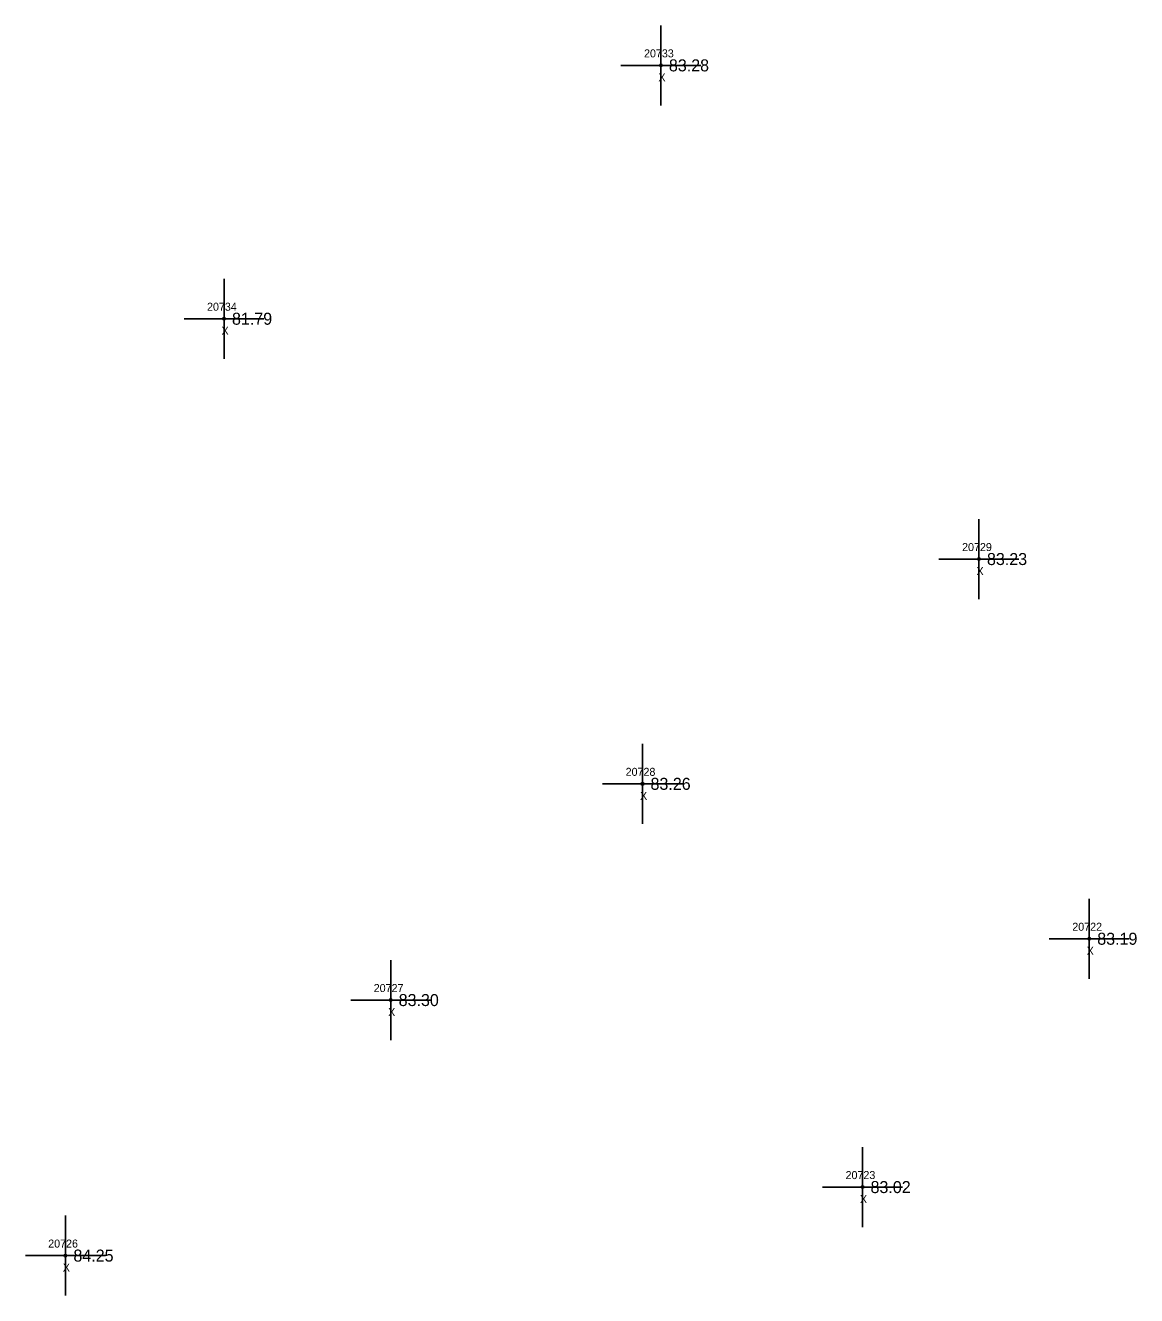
# Model space of a CAD drawing. Extents: x 2530197 to 2532051, y 935230 to 936631.
# Drawn here: x 2530947.8 to 2531086.8, y 936183.2 to 936341.9 of the extents above; entities that cross this region are included whole.
import ezdxf

# ---------------------------------------------------------------- set-up
doc = ezdxf.new("R2010")
doc.units = 0
for name, color, linetype in [('RD_EX_Misc', 7, 'Continuous'), ('RD_EX_Misc_txCode', 7, 'Continuous'), ('RD_EX_TX_Misc_ELEV', 7, 'Continuous'), ('RD_SMD_Locator', 7, 'Continuous')]:
    doc.layers.add(name, color=color, linetype=linetype)

msp = doc.modelspace()

# ---------------------------------------------------------------- linework, layer by layer
at = {"layer": 'RD_EX_Misc'}
for p, q in [((2531027.28, 936331.93), (2531027.28, 936341.93)), ((2531022.28, 936336.93), (2531032.28, 936336.93)), ((2530972.65, 936300.27), (2530972.65, 936310.27)), ((2530967.65, 936305.27), (2530977.65, 936305.27)), ((2531067.05, 936270.24), (2531067.05, 936280.24)), ((2531062.05, 936275.24), (2531072.05, 936275.24)), ((2531024.98, 936242.15), (2531024.98, 936252.15)), ((2531019.98, 936247.15), (2531029.98, 936247.15)), ((2531080.84, 936222.79), (2531080.84, 936232.79)), ((2531075.84, 936227.79), (2531085.84, 936227.79)), ((2530993.49, 936215.13), (2530993.49, 936225.13)), ((2530988.49, 936220.13), (2530998.49, 936220.13)), ((2531052.49, 936191.76), (2531052.49, 936201.76)), ((2531047.49, 936196.76), (2531057.49, 936196.76)), ((2530952.82, 936183.2), (2530952.82, 936193.2)), ((2530947.82, 936188.2), (2530957.82, 936188.2))]:
    msp.add_line(p, q, dxfattribs=at)
at = {"layer": 'RD_SMD_Locator'}
for centre in [(2531027.28, 936336.93), (2530972.65, 936305.27), (2531067.05, 936275.24), (2531024.98, 936247.15), (2531080.84, 936227.79), (2530993.49, 936220.13), (2531052.49, 936196.76), (2530952.82, 936188.2)]:
    msp.add_circle(centre, 0.15, dxfattribs=at)

# ---------------------------------------------------------------- texts
at = {"layer": 'RD_EX_Misc_txCode'}
for s, p in [('20733', (2531025.17, 936337.93)), ('X', (2531026.97, 936334.93)), ('20734', (2530970.53, 936306.27)), ('X', (2530972.34, 936303.27)), ('20729', (2531064.94, 936276.24)), ('X', (2531066.74, 936273.24)), ('20728', (2531022.87, 936248.15)), ('X', (2531024.67, 936245.15)), ('20722', (2531078.72, 936228.79)), ('X', (2531080.52, 936225.79)), ('20727', (2530991.37, 936221.13)), ('X', (2530993.17, 936218.13)), ('20723', (2531050.37, 936197.76)), ('X', (2531052.17, 936194.76)), ('20726', (2530950.67, 936189.2)), ('X', (2530952.5, 936186.2))]:
    msp.add_text(s, height=1, dxfattribs=at).set_placement(p)
at = {"layer": 'RD_EX_TX_Misc_ELEV'}
for s, p in [('83.28', (2531028.28, 936336.18)), ('81.79', (2530973.65, 936304.52)), ('83.23', (2531068.05, 936274.49)), ('83.26', (2531025.98, 936246.4)), ('83.19', (2531081.84, 936227.04)), ('83.30', (2530994.49, 936219.38)), ('83.02', (2531053.49, 936196.01)), ('84.25', (2530953.82, 936187.45))]:
    msp.add_text(s, height=1.5, dxfattribs=at).set_placement(p)

doc.saveas('drawing.dxf')
